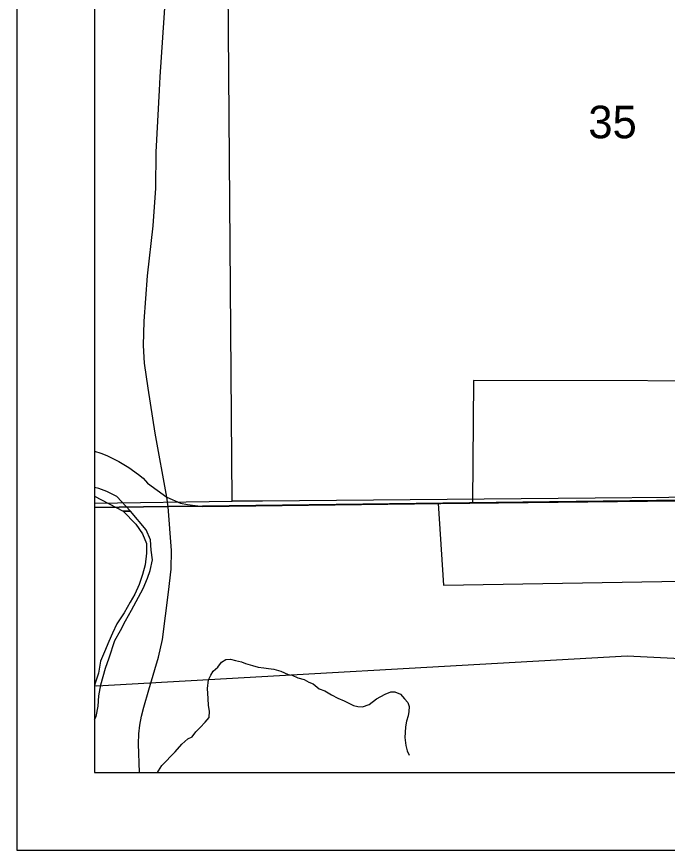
# Model space of a CAD drawing. Extents: x 0 to 36.9, y 0 to 22.
# Drawn here: x 2 to 2.835, y 14 to 15.071 of the extents above; entities that cross this region are included whole.
import ezdxf

# ---------------------------------------------------------------- set-up
doc = ezdxf.new("R2010")
doc.units = 0
for name, color, linetype in [('Default', 7, 'Continuous'), ('GM_X_County_Road', 7, 'Continuous'), ('GM_X_Major_River', 7, 'Continuous'), ('GM_X_Minor_River', 7, 'Continuous'), ('GM_X_Rail_Line', 7, 'Continuous'), ('GM_X_Section', 7, 'Continuous'), ('GM_X_Section_Text', 7, 'Continuous'), ('GM_X_State_Route', 7, 'Continuous'), ('GM_X_Township_Road', 7, 'Continuous'), ('SH_Cut_Line', 7, 'Continuous'), ('SH_Data', 7, 'Continuous')]:
    doc.layers.add(name, color=color, linetype=linetype)

msp = doc.modelspace()

# ---------------------------------------------------------------- linework, layer by layer
at = {"layer": 'Default'}
for points in [[(2.1, 15.4352), (2.1, 14.4458), (2.2767, 14.4483), (2.2688, 15.4372)], [(2.9371, 14.1), (3.7524, 14.1), (3.7505, 14.1647), (3.5419, 14.1659), (3.5348, 14.4558), (3.2921, 14.601), (3.0338, 14.6027), (2.5864, 14.6033), (2.5853, 14.4464), (2.5411, 14.4454), (2.5481, 14.3407), (2.9302, 14.347)]]:
    msp.add_lwpolyline(points, close=True, dxfattribs=at)
at = {"layer": 'GM_X_County_Road'}
for points in [[(2.1833, 14.9764), (2.1842, 14.9933), (2.1948, 15.152), (2.1971, 15.1817), (2.1961, 15.2059), (2.1903, 15.2612), (2.1808, 15.3203), (2.1573, 15.4391), (2.1152, 15.5714), (2.1, 15.651)], [(2.1947, 14.4411), (2.1927, 14.4534), (2.178, 14.5359), (2.1689, 14.5935), (2.1643, 14.6255), (2.1628, 14.6482), (2.1638, 14.6795), (2.1679, 14.738), (2.1751, 14.802), (2.1789, 14.8505), (2.1793, 14.8967), (2.1833, 14.9764)]]:
    msp.add_lwpolyline(points, dxfattribs=at)
at = {"layer": 'GM_X_Major_River'}
msp.add_line((2.146, 14.4357), (2.1366, 14.4356), dxfattribs=at)
for points in [[(2.1, 14.1675), (2.102, 14.1717), (2.1048, 14.185), (2.1057, 14.1983), (2.1081, 14.2124), (2.1139, 14.2341), (2.1186, 14.2471), (2.1262, 14.2693), (2.1332, 14.2823), (2.1398, 14.2949), (2.1476, 14.3083), (2.1623, 14.3362), (2.1678, 14.3496), (2.1714, 14.3595), (2.1742, 14.3729), (2.1725, 14.3857), (2.1719, 14.3986), (2.1662, 14.4118), (2.146, 14.4357)], [(2.1366, 14.4356), (2.153, 14.4188), (2.1615, 14.4064), (2.1667, 14.394), (2.1669, 14.3815), (2.1652, 14.3667), (2.1616, 14.3541), (2.1573, 14.3415), (2.1518, 14.3292), (2.1459, 14.3185), (2.1381, 14.3051), (2.1285, 14.2909), (2.123, 14.2787), (2.1182, 14.2684), (2.1128, 14.255), (2.1077, 14.2428), (2.1049, 14.2275), (2.1012, 14.2161), (2.1, 14.2118)], [(2.146, 14.4357), (2.1366, 14.4356)]]:
    msp.add_lwpolyline(points, dxfattribs=at)
at = {"layer": 'GM_X_Minor_River'}
for p, q in [((2.1, 14.4548), (2.1366, 14.4356)), ((2.1366, 14.4356), (2.146, 14.4357))]:
    msp.add_line(p, q, dxfattribs=at)
for points in [[(2.146, 14.4357), (2.1286, 14.4546), (2.1156, 14.4609), (2.1053, 14.4645), (2.1, 14.4659)], [(2.1808, 14.1), (2.182, 14.1022), (2.1864, 14.1088), (2.2035, 14.1266), (2.212, 14.1363), (2.2198, 14.1434), (2.2254, 14.1458), (2.2302, 14.1523), (2.2358, 14.1578), (2.2421, 14.1648), (2.2472, 14.1706), (2.2475, 14.1786), (2.2465, 14.1858), (2.246, 14.1949), (2.245, 14.2078), (2.2462, 14.2188), (2.2491, 14.225), (2.2524, 14.23), (2.2584, 14.2351), (2.2632, 14.2416), (2.2684, 14.2452), (2.2745, 14.2457), (2.2809, 14.2439), (2.2886, 14.2422), (2.2939, 14.24), (2.3027, 14.2372), (2.3099, 14.2354), (2.3175, 14.2345), (2.3232, 14.2334), (2.3304, 14.2325), (2.3392, 14.23), (2.3487, 14.226), (2.3537, 14.225), (2.3609, 14.2217), (2.3693, 14.2192), (2.3751, 14.2159), (2.3808, 14.2138), (2.3885, 14.2075), (2.3958, 14.205), (2.4042, 14.1995), (2.4126, 14.1955), (2.4207, 14.1918), (2.4325, 14.186), (2.4379, 14.1846), (2.4439, 14.1843), (2.4526, 14.1872), (2.4619, 14.1946), (2.4675, 14.1974), (2.4731, 14.2006), (2.4806, 14.2034), (2.4856, 14.2035), (2.4928, 14.2006), (2.4982, 14.1947), (2.5021, 14.1898), (2.5038, 14.1849), (2.5035, 14.1784), (2.5025, 14.1727), (2.5007, 14.1658), (2.4994, 14.1586), (2.4988, 14.1513), (2.4985, 14.1448), (2.4995, 14.1346), (2.5015, 14.1278), (2.5039, 14.1221)]]:
    msp.add_lwpolyline(points, dxfattribs=at)
at = {"layer": 'GM_X_Rail_Line'}
for points in [[(2.1, 20.4802), (2.1, 14.4405), (2.1945, 14.4417), (2.2387, 14.4422), (2.9245, 14.4504)], [(2.9245, 14.4504), (2.2387, 14.4422), (2.1945, 14.4417), (2.1, 14.4405), (2.1, 14.1), (4.2643, 14.1)], [(3.311, 14.1), (3.2736, 14.1183), (3.0154, 14.2168), (2.8525, 14.2458), (2.7837, 14.2492), (2.103, 14.2109), (2.1, 14.2111)]]:
    msp.add_lwpolyline(points, dxfattribs=at)
at = {"layer": 'GM_X_Section'}
msp.add_lwpolyline([(2.2688, 15.4372), (3.2569, 15.4522), (3.2645, 14.457), (2.3157, 14.4485), (2.2767, 14.4483)], close=True, dxfattribs=at)
at = {"layer": 'GM_X_State_Route'}
for p, q in [((2.2389, 14.4417), (2.5447, 14.4453)), ((2.5447, 14.4453), (2.5818, 14.4458)), ((2.5818, 14.4458), (2.6189, 14.4462))]:
    msp.add_line(p, q, dxfattribs=at)
for points in [[(2.1, 14.5128), (2.1081, 14.5101), (2.1159, 14.5069), (2.1311, 14.4995), (2.1439, 14.4918), (2.1565, 14.4828), (2.1626, 14.4778), (2.1681, 14.4716), (2.1927, 14.4534)], [(2.6189, 14.4462), (2.9247, 14.4499), (2.9577, 14.4503), (2.9638, 14.4503), (2.988, 14.4506), (2.9998, 14.4508), (3.021, 14.451), (3.0416, 14.4513), (3.0665, 14.4516), (3.0981, 14.4514), (3.1214, 14.4516), (3.1494, 14.4521), (3.178, 14.4527), (3.2079, 14.4532), (3.2373, 14.454), (3.2986, 14.4542), (3.3028, 14.4544), (3.3338, 14.4548), (3.3432, 14.455), (3.3779, 14.4551), (3.4048, 14.4554), (3.4458, 14.4559), (3.4636, 14.4561), (3.4746, 14.4562)], [(2.1927, 14.4534), (2.2103, 14.446), (2.2194, 14.4443), (2.2389, 14.4417)]]:
    msp.add_lwpolyline(points, dxfattribs=at)
at = {"layer": 'GM_X_Township_Road'}
msp.add_lwpolyline([(2.1576, 14.1), (2.1564, 14.1367), (2.1568, 14.1497), (2.1581, 14.1607), (2.1604, 14.1723), (2.1634, 14.1838), (2.1696, 14.2063), (2.1775, 14.2322), (2.182, 14.2479), (2.1873, 14.2708), (2.1949, 14.3316), (2.1982, 14.3611), (2.1988, 14.3849), (2.1947, 14.4411)], dxfattribs=at)
at = {"layer": 'SH_Cut_Line'}
for points in [[(2.1, 20.9), (2.1, 14.4405), (2.1945, 14.4417), (2.2387, 14.4422), (2.9245, 14.4504)], [(2.9245, 14.4504), (2.2387, 14.4422), (2.1945, 14.4417), (2.1, 14.4405), (2.1, 14.1), (8.9, 14.1)]]:
    msp.add_lwpolyline(points, dxfattribs=at)
at = {"layer": 'SH_Data'}
for p, q in [((2, 21), (2, 14)), ((2.1, 20.9), (2.1, 14.1)), ((2.1, 14.1), (8.9, 14.1)), ((2.1, 14.1), (2.1, 14.1)), ((2, 14), (9, 14))]:
    msp.add_line(p, q, dxfattribs=at)

# ---------------------------------------------------------------- texts
at = {"layer": 'GM_X_Section_Text'}
msp.add_text('35', height=0.04186, rotation=0, dxfattribs=at).set_placement((2.734, 14.9145))

doc.saveas('drawing.dxf')
